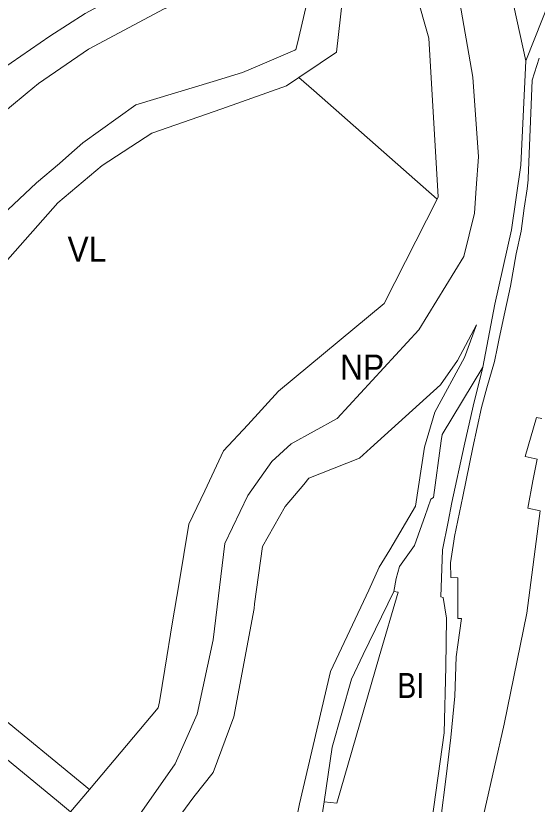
# Model space of a CAD drawing. Extents: x -650451 to -642268, y -1075216 to -1066610.
# Drawn here: x -646163.1 to -645913.4, y -1069919.7 to -1069542.2 of the extents above; entities that cross this region are included whole.
import ezdxf

# ---------------------------------------------------------------- set-up
doc = ezdxf.new("R2010")
doc.units = 0
doc.header["$LTSCALE"] = 4.8
for name, color, linetype, lineweight in [('15', 7, 'Continuous', 13), ('2', 7, 'Continuous', 13), ('25', 7, 'Continuous', 13), ('34', 7, 'Continuous', 13), ('35', 7, 'Continuous', 13), ('41', 7, 'Continuous', 13), ('43', 7, 'Continuous', 13), ('45', 7, 'Continuous', 13), ('48', 7, 'Continuous', 13)]:
    doc.layers.add(name, color=color, linetype=linetype, lineweight=lineweight)
doc.layers.add('62', color=7, linetype='Continuous')

msp = doc.modelspace()

# ---------------------------------------------------------------- linework, layer by layer
at = {"layer": '15'}
for points in [[(-645918.82, -1069563.81), (-645910.9, -1069543.64), (-645897.92, -1069511.49), (-645884.01, -1069481.56), (-645875.02, -1069468.52), (-645869.91, -1069451.02)], [(-646200.67, -1069752.88), (-646203.82, -1069728.79), (-646207.96, -1069697.21), (-646205.34, -1069680.08), (-646195.87, -1069662.74), (-646176.16, -1069644.04), (-646169.42, -1069637.65), (-646166.94, -1069635.16), (-646153.18, -1069622.24), (-646142.14, -1069612.9), (-646137.61, -1069608.96), (-646130.94, -1069603.1), (-646105.58, -1069584.91), (-646068.61, -1069573.63), (-646054.54, -1069569.34), (-646046.26, -1069565.81), (-646029.48, -1069558.67), (-646028.96, -1069558.45), (-646028.24, -1069555.37), (-646018.55, -1069514.14), (-646017.63, -1069499.08)], [(-646004.7, -1069517.16), (-646009.52, -1069559.6), (-646017.39, -1069564.94), (-646027.49, -1069571.79)], [(-645912.51, -1069562.49), (-645915.79, -1069573.09), (-645917.68, -1069620.16), (-645917.74, -1069620.86), (-645918.23, -1069625.11), (-645919.6, -1069634.34), (-645921.13, -1069645.4), (-645923.49, -1069656.16), (-645926.22, -1069671.74), (-645929.67, -1069687.75), (-645931.77, -1069697.53), (-645932.41, -1069700.69), (-645933.83, -1069707.8), (-645937.55, -1069720.4), (-645940.1, -1069729.8), (-645944.19, -1069748.94), (-645948.99, -1069772.41), (-645953.05, -1069791.5), (-645953.4, -1069793.8), (-645954.96, -1069804.13), (-645954.79, -1069811.15), (-645951.38, -1069811.33), (-645951.42, -1069830.72), (-645949.58, -1069830.77), (-645951.37, -1069843.39), (-645952.27, -1069849.2), (-645952.79, -1069868), (-645954.82, -1069887.72), (-645957.04, -1069906.36), (-645959.68, -1069927.82)], [(-645939.36, -1069710.47), (-645933.68, -1069680.28), (-645925.69, -1069644.69), (-645921.18, -1069613.78), (-645918.82, -1069563.81)], [(-646027.49, -1069571.79), (-646033.46, -1069575.84), (-646064.48, -1069586.72), (-646097.88, -1069598.43), (-646121.76, -1069613.94), (-646142.99, -1069631.85), (-646168.19, -1069660.3), (-646181.86, -1069675.73), (-646188.9, -1069692.13), (-646190.58, -1069708.64), (-646187.15, -1069740.55), (-646186.2, -1069749.43), (-646187.53, -1069750.63), (-646186.24, -1069769.06), (-646186.66, -1069775.09), (-646187.9, -1069781.01), (-646188.76, -1069783.97), (-646187.68, -1069788.27), (-646188.83, -1069794.63), (-646222.694, -1069834.722), (-646231.73, -1069845.42)], [(-645963.78, -1069927.8), (-645957.97, -1069885.45), (-645957.1, -1069853.97), (-645956.81, -1069830.65), (-645958.46, -1069820.67), (-645959.56, -1069820.45), (-645958.82, -1069797.9), (-645956.06, -1069784.57), (-645954.27, -1069775.33), (-645948.32, -1069748.06), (-645944.06, -1069729.12), (-645939.36, -1069710.47)]]:
    msp.add_lwpolyline(points, dxfattribs=at)
at = {"layer": '2'}
for points in [[(-645959.68, -1069927.82), (-645957.04, -1069906.36), (-645954.82, -1069887.72), (-645952.79, -1069868), (-645952.27, -1069849.2), (-645951.37, -1069843.39), (-645949.58, -1069830.77), (-645951.42, -1069830.72), (-645951.38, -1069811.33), (-645954.79, -1069811.15), (-645954.96, -1069804.13), (-645953.4, -1069793.8), (-645953.05, -1069791.5), (-645948.99, -1069772.41), (-645944.19, -1069748.94), (-645940.1, -1069729.8), (-645937.55, -1069720.4), (-645933.83, -1069707.8), (-645932.41, -1069700.69), (-645931.77, -1069697.53), (-645929.67, -1069687.75), (-645926.22, -1069671.74), (-645923.49, -1069656.16), (-645921.13, -1069645.4), (-645919.6, -1069634.34), (-645918.23, -1069625.11), (-645917.74, -1069620.86), (-645917.68, -1069620.16), (-645915.79, -1069573.09), (-645912.51, -1069562.49)], [(-645982.12, -1069817.85), (-645980.87, -1069811.56), (-645979.38, -1069805.93), (-645972.16, -1069795.77), (-645968.57, -1069785.9), (-645967.15, -1069781.97), (-645964.34, -1069773.6), (-645963.06, -1069772.82), (-645959.35, -1069745.74), (-645958.9, -1069742.7), (-645939.36, -1069710.47)], [(-645939.36, -1069710.47), (-645944.06, -1069729.12), (-645948.32, -1069748.06), (-645954.27, -1069775.33), (-645956.06, -1069784.57), (-645958.82, -1069797.9), (-645959.56, -1069820.45), (-645958.46, -1069820.67), (-645956.81, -1069830.65), (-645957.1, -1069853.97), (-645957.97, -1069885.45), (-645963.78, -1069927.8)], [(-645911.19, -1069734.97), (-645913.78, -1069734.57), (-645919.21, -1069753.23), (-645913.36, -1069754.55), (-645915.56, -1069764.88), (-645917.9, -1069778.03), (-645911.909, -1069779.311), (-645918.332, -1069828.187), (-645929.263, -1069881.347), (-645947.741, -1069963.127)], [(-646015.46, -1069918.63), (-646009.34, -1069919.12), (-645989.11, -1069849.11), (-645979.96, -1069818.11), (-645982.12, -1069817.85)], [(-646035.42, -1069980.12), (-646029.65, -1069960.92), (-646018.88, -1069941.32), (-646015.46, -1069918.63)]]:
    msp.add_lwpolyline(points, dxfattribs=at)
at = {"layer": '25'}
for points in [[(-646169.9, -1069568.04), (-646146.81, -1069551.97), (-646129.87, -1069541.19), (-646112.56, -1069531.78), (-646094.39, -1069523.34), (-646075.48, -1069516.38), (-646020.75, -1069500), (-646017.63, -1069499.08), (-646018.55, -1069514.14)], [(-646018.55, -1069514.14), (-646056.24, -1069525.54), (-646085.67, -1069536.53), (-646091.98, -1069538.88), (-646128.27, -1069558.17), (-646152.27, -1069574.59), (-646157.69, -1069579.08), (-646183.24, -1069600.22), (-646193.38, -1069608.83), (-646186.23, -1069623.04), (-646197.52, -1069612.3), (-646203.35, -1069617.55), (-646232.98, -1069657.69), (-646244.03, -1069670.61), (-646263.66, -1069694.78), (-646265.02, -1069696.43)]]:
    msp.add_lwpolyline(points, dxfattribs=at)
at = {"layer": '34'}
for points in [[(-646222.694, -1069834.722), (-646188.83, -1069794.63), (-646187.68, -1069788.27), (-646188.76, -1069783.97), (-646187.9, -1069781.01), (-646186.66, -1069775.09), (-646186.24, -1069769.06), (-646187.53, -1069750.63), (-646186.2, -1069749.43), (-646187.15, -1069740.55), (-646190.58, -1069708.64), (-646188.9, -1069692.13), (-646181.86, -1069675.73), (-646168.19, -1069660.3), (-646142.99, -1069631.85), (-646121.76, -1069613.94), (-646097.88, -1069598.43), (-646064.48, -1069586.72), (-646033.46, -1069575.84), (-646027.49, -1069571.79)], [(-646027.49, -1069571.79), (-646020.4, -1069578.04), (-645961.36, -1069630.05)], [(-645961.36, -1069630.05), (-645986.71, -1069679.91), (-646037.33, -1069721.89), (-646051.95, -1069738.02), (-646063.59, -1069750.57), (-646072.6, -1069769.62), (-646080.14, -1069785.63), (-646085.07, -1069814.68), (-646088.02, -1069832.44), (-646091.72, -1069854.99), (-646094.33, -1069870.67), (-646094.82, -1069873.63), (-646127.84, -1069912.695), (-646222.694, -1069834.722)], [(-646231.73, -1069845.42), (-646203.48, -1069868.65), (-646142.68, -1069918.62), (-646136.88, -1069923.39)]]:
    msp.add_lwpolyline(points, dxfattribs=at)
at = {"layer": '35'}
for points in [[(-646265.02, -1069696.43), (-646263.66, -1069694.78), (-646244.03, -1069670.61), (-646232.98, -1069657.69), (-646203.35, -1069617.55), (-646197.52, -1069612.3), (-646186.23, -1069623.04), (-646193.38, -1069608.83), (-646183.24, -1069600.22), (-646157.69, -1069579.08), (-646152.27, -1069574.59), (-646128.27, -1069558.17), (-646091.98, -1069538.88), (-646085.67, -1069536.53), (-646056.24, -1069525.54), (-646018.55, -1069514.14)], [(-646018.55, -1069514.14), (-646028.24, -1069555.37), (-646028.96, -1069558.45), (-646029.48, -1069558.67), (-646046.26, -1069565.81), (-646054.54, -1069569.34), (-646068.61, -1069573.63), (-646105.58, -1069584.91), (-646130.94, -1069603.1), (-646137.61, -1069608.96), (-646142.14, -1069612.9), (-646153.18, -1069622.24), (-646166.94, -1069635.16), (-646169.42, -1069637.65), (-646176.16, -1069644.04), (-646195.87, -1069662.74), (-646205.34, -1069680.08), (-646207.96, -1069697.21), (-646203.82, -1069728.79), (-646200.67, -1069752.88), (-646265.02, -1069696.43)]]:
    msp.add_lwpolyline(points, dxfattribs=at)
at = {"layer": '41'}
for points in [[(-646015.46, -1069918.63), (-646011.51, -1069892.38), (-646002.25, -1069859.77), (-645996.72, -1069847.96), (-645982.12, -1069817.85)], [(-645982.12, -1069817.85), (-645979.96, -1069818.11), (-645989.11, -1069849.11), (-646009.34, -1069919.12), (-646015.46, -1069918.63)]]:
    msp.add_lwpolyline(points, dxfattribs=at)
at = {"layer": '43'}
msp.add_lwpolyline([(-645947.741, -1069963.127), (-645929.263, -1069881.347), (-645918.332, -1069828.187), (-645911.909, -1069779.311), (-645917.9, -1069778.03), (-645915.56, -1069764.88), (-645913.36, -1069754.55), (-645919.21, -1069753.23), (-645913.78, -1069734.57), (-645911.19, -1069734.97)], dxfattribs=at)
at = {"layer": '45'}
for points in [[(-645957.35, -1069496.35), (-645958.57, -1069492.51), (-645958.72, -1069492.05), (-645935, -1069485.04), (-645934.97, -1069490.31), (-645918.82, -1069563.81)], [(-646124.96, -1069959.99), (-646121.75, -1069950.24), (-646086.68, -1069900.4), (-646076.24, -1069876.52), (-646068.64, -1069840.94), (-646062.91, -1069794.85), (-646051.95, -1069771.98), (-646040.53, -1069755.58), (-646031.15, -1069747.2), (-646009.2, -1069734.98), (-645970.08, -1069692.61), (-645948.61, -1069657.43), (-645943.44, -1069636.76), (-645942.58, -1069624.73), (-645941.5, -1069609.76), (-645944.19, -1069571.66), (-645957.35, -1069496.35)], [(-645918.82, -1069563.81), (-645921.18, -1069613.78), (-645925.69, -1069644.69), (-645933.68, -1069680.28), (-645939.36, -1069710.47)], [(-646030.62, -1069936.3), (-646027.3, -1069919.47), (-646012.37, -1069856.22), (-646003.18, -1069836.56), (-645993.96, -1069817.23), (-645989.01, -1069806.25), (-645983.89, -1069797.86), (-645971.7, -1069777.05), (-645968.78, -1069758.13), (-645967.35, -1069748.81), (-645962.48, -1069732.04), (-645948.22, -1069705.79), (-645942.41, -1069690.26), (-645951.52, -1069707.28), (-645959.63, -1069718.95), (-645993.22, -1069749.24), (-645998.57, -1069754.06), (-646022.72, -1069763.59), (-646025.11, -1069766.63), (-646034.02, -1069777.19), (-646044.94, -1069796.35), (-646048.71, -1069823.79), (-646049, -1069825.93), (-646058.71, -1069877.82), (-646068.5, -1069904.5), (-646077.78, -1069916.11), (-646104.04, -1069951.75)], [(-645939.36, -1069710.47), (-645958.9, -1069742.7), (-645959.35, -1069745.74), (-645963.06, -1069772.82), (-645964.34, -1069773.6), (-645967.15, -1069781.97), (-645968.57, -1069785.9), (-645972.16, -1069795.77), (-645979.38, -1069805.93), (-645980.87, -1069811.56), (-645982.12, -1069817.85)], [(-645982.12, -1069817.85), (-645996.72, -1069847.96), (-646002.25, -1069859.77), (-646011.51, -1069892.38), (-646015.46, -1069918.63)], [(-646015.46, -1069918.63), (-646018.88, -1069941.32), (-646029.65, -1069960.92), (-646035.42, -1069980.12)]]:
    msp.add_lwpolyline(points, dxfattribs=at)
at = {"layer": '48'}
for points in [[(-645957.35, -1069496.35), (-645944.19, -1069571.66), (-645941.5, -1069609.76), (-645942.58, -1069624.73), (-645943.44, -1069636.76), (-645948.61, -1069657.43), (-645970.08, -1069692.61), (-646009.2, -1069734.98), (-646031.15, -1069747.2), (-646040.53, -1069755.58), (-646051.95, -1069771.98), (-646062.91, -1069794.85), (-646068.64, -1069840.94), (-646076.24, -1069876.52), (-646086.68, -1069900.4), (-646121.75, -1069950.24), (-646124.96, -1069959.99)], [(-645961.36, -1069630.05), (-645960.78, -1069628.91), (-645965.36, -1069552.99), (-645977.73, -1069509.11), (-646004.7, -1069517.16), (-646003.89, -1069510.07), (-645957.35, -1069496.35)], [(-646127.84, -1069912.695), (-646094.82, -1069873.63), (-646094.33, -1069870.67), (-646091.72, -1069854.99), (-646088.02, -1069832.44), (-646085.07, -1069814.68), (-646080.14, -1069785.63), (-646072.6, -1069769.62), (-646063.59, -1069750.57), (-646051.95, -1069738.02), (-646037.33, -1069721.89), (-645986.71, -1069679.91), (-645961.36, -1069630.05)], [(-646160.09, -1069997.51), (-646152.59, -1069978.9), (-646136.46, -1069938.84), (-646135.28, -1069935.88), (-646131.96, -1069927.57), (-646136.23, -1069923.94), (-646136.88, -1069923.39), (-646127.84, -1069912.695)]]:
    msp.add_lwpolyline(points, dxfattribs=at)

# ---------------------------------------------------------------- texts
at = {"layer": '62'}
for s, width, p in [('VL', 0.95, (-646138.307, -1069659.957)), ('NP', 0.95, (-646007.822, -1069716.41)), ('BI', 0.85, (-645980.427, -1069868.838))]:
    msp.add_text(s, height=12, dxfattribs=dict(at, width=width)).set_placement(p)

doc.saveas('drawing.dxf')
